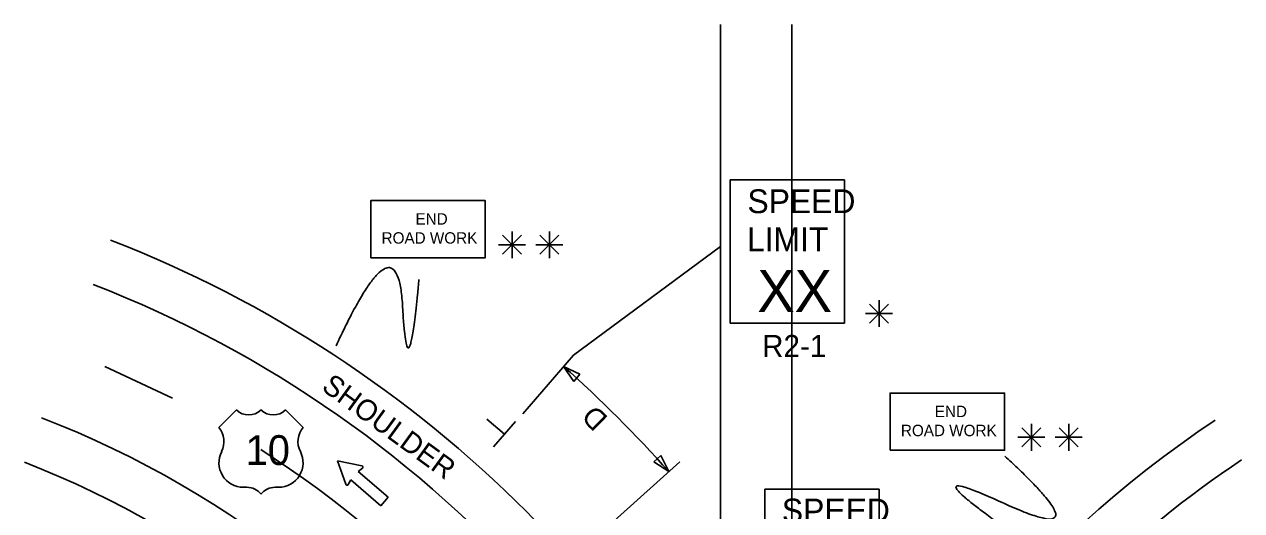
# Model space of a CAD drawing. Extents: x 16303 to 18479, y 5704 to 6974.
# Drawn here: x 16746.9 to 17155.7, y 6811 to 6974.1 of the extents above; entities that cross this region are included whole.
import ezdxf

# ---------------------------------------------------------------- set-up
doc = ezdxf.new("R2010")
doc.units = 0
for name, color, linetype in [('ALI_LEGAL_EX', 7, 'Continuous'), ('MT_SCRATCH_LEVEL_E', 7, 'Continuous'), ('PAVT_EDGE_EX', 7, 'Continuous'), ('TRAFFIC_SIGNS_PR', 7, 'Continuous'), ('TYPICAL_EX', 7, 'Continuous'), ('TYPICAL_TEXT_DIMEN_PR', 7, 'Continuous')]:
    doc.layers.add(name, color=color, linetype=linetype)

msp = doc.modelspace()

# ---------------------------------------------------------------- linework, layer by layer
at = {"layer": 'ALI_LEGAL_EX'}
for p, q in [((16980.68, 6974.12), (16980.68, 6155.98)), ((17004.68, 6974.12), (17004.68, 6155.98)), ((16980.68, 6877.04), (16980.68, 6013.12)), ((17004.68, 6877.04), (17004.68, 6013.12))]:
    msp.add_line(p, q, dxfattribs=at)
for points in [[(17004.68, 6949.12), (17004.68, 6974.12)], [(16796.64, 6848.72), (16773.99, 6859.31)]]:
    msp.add_lwpolyline(points, dxfattribs=at)
msp.add_arc((16629.65, 6525.15), 364, 0, 57.2958, dxfattribs=at)
at = {"layer": 'MT_SCRATCH_LEVEL_E'}
for p, q in [((16860.24, 6826.04), (16852.05, 6827.62)), ((16852.05, 6827.62), (16854.86, 6819.78)), ((16859.05, 6824.09), (16860.45, 6825.23)), ((16869.1, 6815.45), (16859.05, 6824.09)), ((16855.69, 6819.7), (16856.61, 6821.26)), ((16856.61, 6821.26), (16866.66, 6812.61)), ((16866.66, 6812.61), (16869.1, 6815.45))]:
    msp.add_line(p, q, dxfattribs=at)
for centre, start, end in [((16860.15, 6825.59), 309.3361, 79.073), ((16855.3, 6819.95), 199.7248, 329.2637)]:
    msp.add_arc(centre, 0.463, start, end, dxfattribs=at)
at = {"layer": 'PAVT_EDGE_EX'}
for centre, radius, start, end in [((16629.65, 6525.15), 404, 21.0961, 68.7791), ((16629.65, 6525.15), 388, 14.0482, 68.7791), ((16629.65, 6525.15), 340, 0, 68.7791), ((17357.65, 6525.15), 380, 123.6935, 157.5011), ((16629.65, 6525.15), 324, 0, 68.7791), ((17357.65, 6525.15), 364, 123.6935, 165.0045)]:
    msp.add_arc(centre, radius, start, end, dxfattribs=at)
at = {"layer": 'TRAFFIC_SIGNS_PR'}
for p, q in [((16983.99, 6921.9), (17022.39, 6921.9)), ((16983.99, 6873.9), (16983.99, 6921.9)), ((17022.39, 6873.9), (17022.39, 6921.9)), ((16983.99, 6873.9), (17022.39, 6873.9)), ((16995.55, 6818.12), (17033.95, 6818.12)), ((16995.55, 6770.12), (16995.55, 6818.12)), ((17033.95, 6770.12), (17033.95, 6818.12))]:
    msp.add_line(p, q, dxfattribs=at)
for points in [[(16863.28, 6895.8), (16901.68, 6895.8), (16901.68, 6915), (16863.28, 6915)], [(17037.68, 6831.2), (17076.08, 6831.2), (17076.08, 6850.4), (17037.68, 6850.4)]]:
    msp.add_lwpolyline(points, close=True, dxfattribs=at)
at = {"layer": 'TYPICAL_EX'}
for p, q in [((16812.25, 6838.84), (16818.14, 6844.74)), ((16840.55, 6838.84), (16834.65, 6844.74)), ((16820.49, 6818.78), (16821.67, 6818.78)), ((16832.3, 6818.78), (16831.12, 6818.78))]:
    msp.add_line(p, q, dxfattribs=at)
for centre, radius, start, end in [((16822.27, 6849.03), 5.96, 226.1404, 313.8596), ((16830.52, 6849.03), 5.96, 226.1404, 313.8596), ((16806.66, 6834.12), 7.31, 333.0977, 40.1936), ((16846.13, 6834.12), 7.31, 139.8064, 206.9023), ((16820.51, 6827.03), 8.24, 152.6698, 269.9013), ((16832.29, 6827.03), 8.24, 270.0987, 27.3302), ((16821.69, 6812.88), 5.91, 37.1038, 90.1385), ((16831.11, 6812.88), 5.91, 89.8615, 142.8962)]:
    msp.add_arc(centre, radius, start, end, dxfattribs=at)
at = {"layer": 'TYPICAL_TEXT_DIMEN_PR'}
for p, q in [((16910.7, 6900.17), (16910.7, 6904.63)), ((16923.26, 6900.17), (16923.26, 6904.63)), ((16907.51, 6903.36), (16913.89, 6896.98)), ((16913.89, 6903.36), (16907.51, 6896.98)), ((16920.07, 6903.36), (16926.44, 6896.98)), ((16926.44, 6903.36), (16920.07, 6896.98)), ((16910.7, 6900.17), (16906.17, 6900.17)), ((16910.7, 6900.17), (16913.89, 6900.17)), ((16910.7, 6900.17), (16915.18, 6900.17)), ((16910.7, 6900.17), (16910.7, 6895.67)), ((16923.26, 6900.17), (16918.72, 6900.17)), ((16923.26, 6900.17), (16926.44, 6900.17)), ((16923.26, 6900.17), (16927.73, 6900.17)), ((16923.26, 6900.17), (16923.26, 6895.67)), ((16931.32, 6863.17), (16980.76, 6899.6)), ((17030.79, 6880.28), (17037.17, 6873.9)), ((17037.17, 6880.28), (17030.79, 6873.9)), ((17033.98, 6877.09), (17033.98, 6881.55)), ((17033.98, 6877.09), (17029.44, 6877.09)), ((17033.98, 6877.09), (17037.17, 6877.09)), ((17033.98, 6877.09), (17038.46, 6877.09)), ((17033.98, 6877.09), (17033.98, 6872.59)), ((16931.32, 6863.17), (16914.34, 6843.48)), ((16931.42, 6854.32), (16928.01, 6859.34)), ((16928.01, 6859.34), (16933.48, 6856.7)), ((16932.45, 6855.51), (16931.42, 6854.32)), ((16933.48, 6856.7), (16932.45, 6855.51)), ((16908.16, 6836.56), (16902.26, 6841.65)), ((16911.83, 6840.82), (16904.48, 6832.31)), ((17085.1, 6835.57), (17085.1, 6840.03)), ((17097.66, 6835.57), (17097.66, 6840.03)), ((17085.1, 6835.57), (17080.57, 6835.57)), ((17081.92, 6838.76), (17088.29, 6832.38)), ((17088.29, 6838.76), (17081.92, 6832.38)), ((17085.1, 6835.57), (17088.29, 6835.57)), ((17085.1, 6835.57), (17089.58, 6835.57)), ((17085.1, 6835.57), (17085.1, 6831.07)), ((17097.66, 6835.57), (17093.13, 6835.57)), ((17094.47, 6838.76), (17100.85, 6832.38)), ((17100.85, 6838.76), (17094.47, 6832.38)), ((17097.66, 6835.57), (17100.85, 6835.57)), ((17097.66, 6835.57), (17102.14, 6835.57)), ((17097.66, 6835.57), (17097.66, 6831.07)), ((16967.1, 6827.36), (16923.44, 6788.26)), ((16958.3, 6827.35), (16959.47, 6828.39)), ((16963.38, 6824.03), (16958.3, 6827.35)), ((16959.47, 6828.39), (16960.64, 6829.44)), ((16960.64, 6829.44), (16963.38, 6824.03))]:
    msp.add_line(p, q, dxfattribs=at)
msp.add_arc((16629.65, 6525.15), 448, 41.8471, 48.2417, dxfattribs=at)
for points in [[(16851.6, 6866.22), (16872.23, 6911.03), (16875.68, 6847.69), (16879.45, 6888.56)], [(17086.35, 6798.24), (17039.53, 6830.07), (17110.85, 6797.33), (17076.24, 6829.21)]]:
    msp.add_open_spline(points, degree=2, dxfattribs=at)

# ---------------------------------------------------------------- texts
at = {"layer": 'TRAFFIC_SIGNS_PR'}
for s, height, p in [('SPEED', 8, (16989.76, 6910.77)), ('END', 3.831, (16878.28, 6906.92)), ('LIMIT', 8, (16989.59, 6897.97)), ('ROAD WORK', 3.831, (16866.89, 6900.54)), ('XX', 14.031, (16993.1, 6877.66)), ('R2-1', 7.44, (16994.67, 6862.46)), ('END', 3.831, (17052.68, 6842.32)), ('ROAD WORK', 3.831, (17041.29, 6835.94)), ('SPEED', 8, (17001.31, 6806.98))]:
    msp.add_text(s, height=height, dxfattribs=at).set_placement(p)
at = {"layer": 'TYPICAL_EX'}
msp.add_text('10', height=10, dxfattribs=at).set_placement((16821.24, 6826.27))
at = {"layer": 'TYPICAL_TEXT_DIMEN_PR'}
for s, rotation, p in [('SHOULDER', 323.9582, (16846.36, 6851.66)), ('D', 135.5356, (16943.28, 6842.1))]:
    msp.add_text(s, height=7, rotation=rotation, dxfattribs=at).set_placement(p)

doc.saveas('drawing.dxf')
